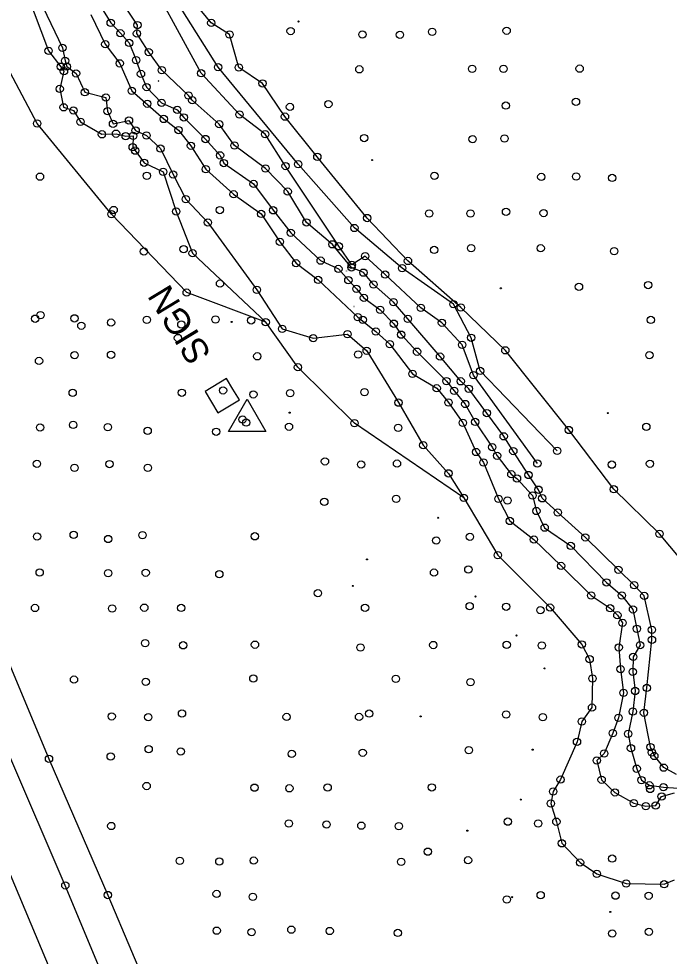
# Model space of a CAD drawing. Extents: x 20503438 to 20508873, y 7964251 to 7984667.
# Drawn here: x 20506200.2 to 20506378.1, y 7975825.9 to 7976082.3 of the extents above; entities that cross this region are included whole.
import ezdxf

# ---------------------------------------------------------------- set-up
doc = ezdxf.new("R2010")
doc.units = 0
for name, color, linetype in [('SurBreakLine', 7, 'Continuous'), ('SurControl', 7, 'Continuous'), ('SurDrainageArrowUp', 7, 'Continuous'), ('SurEdgeRoadPaved', 7, 'Continuous'), ('SurPointsNonDTM', 7, 'Continuous'), ('SurRoadPoints', 7, 'Continuous'), ('SurROWRail', 7, 'Continuous'), ('SurSurveyPoints', 7, 'Continuous'), ('SurTopOfWater', 7, 'Continuous')]:
    doc.layers.add(name, color=color, linetype=linetype)

msp = doc.modelspace()

# ---------------------------------------------------------------- linework, layer by layer
at = {"layer": 'SurBreakLine'}
for points in [[(20505948.4, 7976440.27), (20505966.85, 7976397.06), (20506023.36, 7976261.75), (20506041.13, 7976219.76), (20506046.8, 7976206.26), (20506065.51, 7976161.54), (20506080.11, 7976126.62), (20506096.34, 7976088.07), (20506109.89, 7976056.1), (20506152.29, 7975956.2), (20506170.93, 7975911.54), (20506188.78, 7975869.57), (20506237.85, 7975752.64), (20506255.76, 7975710.06), (20506257.96, 7975704.85), (20506266.89, 7975683.65), (20506275.92, 7975662.23), (20506291.46, 7975625.08), (20506306.43, 7975588.4), (20506320.89, 7975553.64), (20506349.14, 7975482.98), (20506362.94, 7975447.73)], [(20506321.91, 7975951.28), (20506292.04, 7975971.7), (20506276.55, 7975986.99), (20506267.72, 7975999.31), (20506246.1, 7976007.41), (20506225.53, 7976028.87), (20506205.19, 7976053.67), (20506197.03, 7976069.21), (20506190.03, 7976084.37), (20506184.41, 7976093.4), (20506177.2, 7976103.38), (20506168.01, 7976123.8)], [(20506347.48, 7975964.11), (20506326.41, 7975985.98), (20506323.96, 7975995.07), (20506319.08, 7976004.25), (20506305.08, 7976014.1), (20506291.99, 7976025.09), (20506276.63, 7976042.56), (20506254.69, 7976069.09), (20506237.54, 7976096.31), (20506234.05, 7976102.52), (20506225.9, 7976107.8)], [(20506342.05, 7975960.65), (20506324.59, 7975984.81), (20506321.5, 7975993.11), (20506315.95, 7975999.17), (20506310.19, 7976003.24), (20506300.42, 7976012.34), (20506294.96, 7976017.37), (20506291.29, 7976015), (20506287.74, 7976020.08), (20506273.17, 7976042.03), (20506267.6, 7976050.75), (20506260.55, 7976056.13), (20506250.08, 7976067.42), (20506232.79, 7976099.11)], [(20506380.12, 7975875.61), (20506376.63, 7975877.46), (20506374.06, 7975880.65), (20506372.99, 7975883.09), (20506371.22, 7975892.49), (20506371.99, 7975899.27), (20506373.41, 7975912.41), (20506373.4, 7975915.16), (20506371.3, 7975924.44), (20506368.54, 7975927.36), (20506364.22, 7975931.61), (20506355.18, 7975940.45), (20506347.67, 7975947.24), (20506343.39, 7975951.14), (20506342.38, 7975953.5), (20506339.64, 7975957.52), (20506335.47, 7975964.07), (20506332.84, 7975968.1), (20506328.25, 7975974.47), (20506323.28, 7975981.12), (20506321.08, 7975983.15), (20506315.42, 7975989.91), (20506306.62, 7976000.26), (20506302.69, 7976004.82), (20506297.24, 7976009.64), (20506294.46, 7976012.87), (20506291.2, 7976014.32), (20506285.97, 7976020.62), (20506278.88, 7976026.62), (20506273.74, 7976035.04), (20506267.69, 7976041.37), (20506259.2, 7976047.67), (20506255.02, 7976053.46), (20506247.64, 7976060.03), (20506246.6, 7976061.33), (20506239.3, 7976068.27), (20506235.72, 7976073.22), (20506232.49, 7976078.26), (20506232.64, 7976080.6), (20506225.6, 7976091.26)], [(20506381.1, 7975934.72), (20506375.49, 7975941.43), (20506362.97, 7975953.61), (20506350.67, 7975969.83), (20506333.29, 7975991.62), (20506321.12, 7976003.33), (20506306.65, 7976016.07), (20506295.48, 7976027.82), (20506281.85, 7976044.54), (20506273, 7976055.55), (20506266.84, 7976064.65), (20506260.39, 7976069.01), (20506257.81, 7976078.04), (20506252.83, 7976081.18), (20506244.7, 7976091.19)], [(20506202.28, 7976089.62), (20506208.32, 7976073.55), (20506211.69, 7976069.22), (20506212.53, 7976067.98), (20506211.37, 7976063.13), (20506212.44, 7976058.1), (20506215.1, 7976057.24), (20506217.03, 7976054.15), (20506222.92, 7976050.72), (20506226.77, 7976050.89), (20506229.41, 7976050.21), (20506231.48, 7976050.28), (20506231.33, 7976047.2), (20506231.99, 7976046.25), (20506234.45, 7976042.95), (20506239.67, 7976040.44), (20506243.25, 7976029.61), (20506247.73, 7976018.17), (20506267.72, 7975999.31)], [(20506205.75, 7976087.79), (20506212.1, 7976074.39), (20506212.83, 7976070.83), (20506213.32, 7976069.24), (20506215.84, 7976067.38), (20506218.22, 7976062.22), (20506224.01, 7976060.8), (20506224.47, 7976057.05), (20506225.95, 7976053.6), (20506230.32, 7976054.48), (20506232.14, 7976051.76), (20506235.12, 7976050.41), (20506238.92, 7976046.8), (20506242.38, 7976039.73), (20506245.88, 7976032.99), (20506251.92, 7976026.58), (20506265.31, 7976008.18), (20506272.23, 7975997.51), (20506280.74, 7975994.95), (20506290.1, 7975996.06), (20506295.35, 7975991.51), (20506304.05, 7975977.31), (20506310.84, 7975965.69), (20506317.76, 7975957.97), (20506321.91, 7975951.28), (20506331.23, 7975935.61), (20506345.53, 7975921.24), (20506354.23, 7975911.18), (20506356.36, 7975907.13), (20506357.14, 7975901.83), (20506357, 7975893.89), (20506354.2, 7975890.08), (20506352.9, 7975884.52), (20506348.41, 7975874.19), (20506346.37, 7975870.95), (20506345.72, 7975867.65), (20506347.25, 7975862.68), (20506348.75, 7975856.76), (20506353.74, 7975851.48), (20506358.31, 7975848.43), (20506366.37, 7975845.79), (20506376.74, 7975845.56), (20506379.54, 7975846.75)], [(20506219.84, 7976083.45), (20506223.83, 7976075.35), (20506227.78, 7976070.13), (20506231.07, 7976062.59), (20506239.83, 7976054.91), (20506243.85, 7976051.88), (20506247.27, 7976047.59), (20506251.35, 7976041.16), (20506258.95, 7976034.32), (20506266.48, 7976028.93), (20506271.62, 7976021.32), (20506276.03, 7976015.44), (20506282.07, 7976010.88), (20506292.92, 7976000.7), (20506297.88, 7975996.79), (20506301.7, 7975993.31), (20506307.9, 7975985.19), (20506314.51, 7975981.24), (20506317.72, 7975977.36), (20506321.68, 7975971.79), (20506325.28, 7975963.81), (20506327.31, 7975960.94), (20506331.41, 7975951.01), (20506334.53, 7975944.94), (20506341.12, 7975939.87), (20506348.54, 7975932.64), (20506356.77, 7975924.55), (20506361.98, 7975921.06), (20506363.94, 7975919.15), (20506365.37, 7975917.09), (20506364.31, 7975910.36), (20506364.83, 7975904.4), (20506365.64, 7975897.93), (20506364.27, 7975891.09), (20506362.69, 7975886.89), (20506360.35, 7975881.32), (20506358.29, 7975879.43), (20506359.64, 7975874.16), (20506363.28, 7975870.7), (20506368.46, 7975867.73), (20506371.74, 7975866.91), (20506374.43, 7975867.13), (20506376.06, 7975869.56), (20506379.62, 7975870.57)]]:
    msp.add_lwpolyline(points, dxfattribs=at)
at = {"layer": 'SurControl'}
for centre in [(20506276.68, 7976081.57), (20506296.84, 7976043.67), (20506332.07, 7976008.59), (20506258.41, 7975999.4), (20506274.28, 7975974.56), (20506361.31, 7975974.46), (20506314.9, 7975945.83), (20506295.44, 7975934.42), (20506291.55, 7975927.17), (20506325.14, 7975924.27), (20506336.34, 7975913.62), (20506344.02, 7975904.61), (20506310.11, 7975891.47), (20506340.77, 7975882.38), (20506337.51, 7975868.72), (20506322.89, 7975860.22), (20506335.18, 7975842.04), (20506362.01, 7975838)]:
    msp.add_circle(centre, 0.15, dxfattribs=at)
at = {"layer": 'SurDrainageArrowUp'}
msp.add_lwpolyline([(20506222.76, 7976085.29), (20506225.31, 7976081.21), (20506227.96, 7976078.36), (20506230.37, 7976075.71), (20506232.27, 7976071.01), (20506233.6, 7976067.23), (20506235.14, 7976063.64), (20506239.24, 7976059.31), (20506243.53, 7976057.41), (20506245.34, 7976055.35), (20506251.24, 7976049.43), (20506255.24, 7976044.96), (20506256.26, 7976042.85), (20506264.41, 7976037.14), (20506269.78, 7976029.93), (20506274.57, 7976023.8), (20506282.76, 7976016.16), (20506287.61, 7976013.89), (20506290.34, 7976010.8), (20506292.54, 7976008.43), (20506294.6, 7976005.96), (20506299.04, 7976002.7), (20506302.79, 7975998.91), (20506304.77, 7975995.91), (20506309.13, 7975991.25), (20506317.18, 7975983.21), (20506319.3, 7975980.55), (20506322.33, 7975976.94), (20506325.03, 7975972.04), (20506329.72, 7975965.15), (20506331.03, 7975962.79), (20506334.93, 7975957.72), (20506336.48, 7975956.57), (20506340.71, 7975951.9), (20506341.79, 7975947.67), (20506344.05, 7975943.11), (20506351.19, 7975938.11), (20506360.96, 7975928.14), (20506365.17, 7975924.54), (20506368.22, 7975920.75), (20506369.27, 7975915.46), (20506370.15, 7975910.98), (20506368.3, 7975907.79), (20506368.15, 7975903.66), (20506368.8, 7975898.44), (20506368.17, 7975892.8), (20506366.9, 7975886.71), (20506367.67, 7975882.77), (20506369.24, 7975877.18), (20506370.56, 7975874.06), (20506372.71, 7975872.63), (20506376.54, 7975872.14), (20506383.34, 7975871.63)], dxfattribs=at)
at = {"layer": 'SurEdgeRoadPaved'}
for points in [[(20505973.34, 7976438.98), (20505987.53, 7976403.61), (20506003.07, 7976367.49), (20506018.95, 7976328.88), (20506025.44, 7976313.31), (20506044.67, 7976267.48), (20506061.06, 7976228.29), (20506067.76, 7976212.43), (20506081.36, 7976180.25), (20506103.2, 7976128.63), (20506112.1, 7976107.56), (20506128.65, 7976068.25), (20506136.4, 7976049.83), (20506153.65, 7976009.14), (20506168.49, 7975974.01), (20506178.44, 7975950.63), (20506193.04, 7975916.4), (20506208.43, 7975879.89), (20506224.55, 7975842.62), (20506237.48, 7975811.98)], [(20506375.71, 7975448.39), (20506362.64, 7975481.5), (20506329.83, 7975562.96), (20506317.59, 7975593.18), (20506238.7, 7975783.34), (20506212.9, 7975845.26), (20506167.37, 7975951.08), (20506129.46, 7976040.57), (20506122.49, 7976056.94), (20506110.39, 7976085.68), (20506105.99, 7976096.14), (20506091.81, 7976130.11), (20506074.2, 7976171.54), (20506054.82, 7976217.77), (20506019.21, 7976302.51), (20505976.84, 7976403.26), (20505970.11, 7976419.35)]]:
    msp.add_lwpolyline(points, dxfattribs=at)
at = {"layer": 'SurPointsNonDTM'}
for centre in [(20506206.12, 7976001.25), (20506217.28, 7975998.36), (20506243.71, 7975994.99), (20506256.06, 7975980.67), (20506261.4, 7975972.72), (20506262.4, 7975971.85), (20506282.02, 7975925.2), (20506296.02, 7975892.25), (20506312.07, 7975854.48)]:
    msp.add_circle(centre, 1, dxfattribs=at)
at = {"layer": 'SurRoadPoints'}
msp.add_lwpolyline([(20506258.75, 7975980.99), (20506258.75, 7975980.99), (20506256.97, 7975983.92), (20506251.12, 7975980.37), (20506254.67, 7975974.5), (20506260.53, 7975978.05), (20506258.75, 7975980.98)], dxfattribs=at)
at = {"layer": 'SurROWRail'}
msp.add_lwpolyline([(20506262.64, 7975978.27), (20506267.73, 7975969.45), (20506257.55, 7975969.45)], close=True, dxfattribs=at)
at = {"layer": 'SurSurveyPoints'}
for centre in [(20506225.31, 7976081.21), (20506232.64, 7976080.6), (20506252.83, 7976081.18), (20506227.96, 7976078.36), (20506232.49, 7976078.26), (20506257.81, 7976078.04), (20506274.55, 7976078.96), (20506294.18, 7976078.04), (20506304.46, 7976077.93), (20506313.26, 7976078.73), (20506333.65, 7976079.06), (20506212.1, 7976074.39), (20506223.83, 7976075.35), (20506230.37, 7976075.71), (20506208.32, 7976073.55), (20506235.72, 7976073.22), (20506211.69, 7976069.22), (20506212.83, 7976070.83), (20506213.32, 7976069.24), (20506227.78, 7976070.13), (20506232.27, 7976071.01), (20506212.53, 7976067.98), (20506215.84, 7976067.38), (20506233.6, 7976067.23), (20506239.3, 7976068.27), (20506250.08, 7976067.42), (20506254.69, 7976069.09), (20506260.39, 7976069.01), (20506293.34, 7976068.5), (20506324.22, 7976068.62), (20506332.81, 7976068.63), (20506353.62, 7976068.68), (20506266.84, 7976064.65), (20506211.37, 7976063.13), (20506218.22, 7976062.22), (20506231.07, 7976062.59), (20506235.14, 7976063.64), (20506224.01, 7976060.8), (20506235.32, 7976059.09), (20506239.24, 7976059.31), (20506246.6, 7976061.33), (20506247.64, 7976060.03), (20506284.88, 7976058.99), (20506352.62, 7976059.61), (20506212.44, 7976058.1), (20506215.1, 7976057.24), (20506224.47, 7976057.05), (20506243.53, 7976057.41), (20506274.35, 7976058.2), (20506333.42, 7976058.57), (20506217.03, 7976054.15), (20506230.32, 7976054.48), (20506239.83, 7976054.91), (20506245.34, 7976055.35), (20506260.55, 7976056.13), (20506273, 7976055.55), (20506205.19, 7976053.67), (20506225.95, 7976053.6), (20506232.14, 7976051.76), (20506243.85, 7976051.88), (20506255.02, 7976053.46), (20506222.92, 7976050.72), (20506226.77, 7976050.89), (20506229.41, 7976050.21), (20506231.48, 7976050.28), (20506235.12, 7976050.41), (20506251.24, 7976049.43), (20506267.6, 7976050.75), (20506294.68, 7976049.69), (20506324.34, 7976049.37), (20506333.06, 7976049.59), (20506231.33, 7976047.2), (20506231.99, 7976046.25), (20506238.92, 7976046.8), (20506247.27, 7976047.59), (20506259.2, 7976047.67), (20506255.24, 7976044.96), (20506281.85, 7976044.54), (20506234.45, 7976042.95), (20506251.35, 7976041.16), (20506256.26, 7976042.85), (20506267.69, 7976041.37), (20506273.17, 7976042.03), (20506276.63, 7976042.56), (20506205.97, 7976039.13), (20506235.18, 7976039.38), (20506239.67, 7976040.44), (20506242.38, 7976039.73), (20506313.88, 7976039.35), (20506343.13, 7976039.06), (20506352.66, 7976039.16), (20506362.51, 7976038.78), (20506264.41, 7976037.14), (20506258.95, 7976034.32), (20506273.74, 7976035.04), (20506245.88, 7976032.99), (20506225.53, 7976028.87), (20506226.12, 7976030.01), (20506243.25, 7976029.61), (20506255.17, 7976029.99), (20506266.48, 7976028.93), (20506269.78, 7976029.93), (20506312.46, 7976029.05), (20506323.77, 7976029.07), (20506333.48, 7976029.5), (20506343.76, 7976029.17), (20506251.92, 7976026.58), (20506278.88, 7976026.62), (20506295.48, 7976027.82), (20506274.57, 7976023.8), (20506291.99, 7976025.09), (20506271.62, 7976021.32), (20506285.97, 7976020.62), (20506234.41, 7976018.66), (20506245.27, 7976019.31), (20506247.73, 7976018.17), (20506287.74, 7976020.08), (20506313.8, 7976019.09), (20506323.92, 7976019.59), (20506342.97, 7976019.54), (20506363.06, 7976018.73), (20506276.03, 7976015.44), (20506282.76, 7976016.16), (20506294.96, 7976017.37), (20506306.65, 7976016.07), (20506287.61, 7976013.89), (20506291.2, 7976014.32), (20506291.29, 7976015), (20506294.46, 7976012.87), (20506305.08, 7976014.1), (20506282.07, 7976010.88), (20506290.34, 7976010.8), (20506300.42, 7976012.34), (20506255.22, 7976009.87), (20506265.31, 7976008.18), (20506292.54, 7976008.43), (20506297.24, 7976009.64), (20506353.44, 7976009.01), (20506372.35, 7976009.48), (20506246.1, 7976007.41), (20506294.6, 7976005.96), (20506299.04, 7976002.7), (20506302.69, 7976004.82), (20506310.19, 7976003.24), (20506319.08, 7976004.25), (20506321.12, 7976003.33), (20506204.66, 7976000.28), (20506215.39, 7976000.37), (20506235.22, 7975999.97), (20506253.97, 7976000.06), (20506292.92, 7976000.7), (20506294.27, 7975999.97), (20506306.62, 7976000.26), (20506373.08, 7975999.94), (20506225.41, 7975999.21), (20506244.64, 7975998.69), (20506263.76, 7975999.82), (20506267.72, 7975999.31), (20506272.23, 7975997.51), (20506302.79, 7975998.91), (20506315.95, 7975999.17), (20506280.74, 7975994.95), (20506290.1, 7975996.06), (20506297.88, 7975996.79), (20506304.77, 7975995.91), (20506323.96, 7975995.07), (20506301.7, 7975993.31), (20506321.5, 7975993.11), (20506215.44, 7975990.31), (20506225.4, 7975990.38), (20506265.42, 7975989.99), (20506293.04, 7975990.47), (20506295.35, 7975991.51), (20506309.13, 7975991.25), (20506315.42, 7975989.91), (20506333.29, 7975991.62), (20506372.71, 7975990.28), (20506205.7, 7975988.72), (20506276.55, 7975986.99), (20506307.9, 7975985.19), (20506324.59, 7975984.81), (20506326.41, 7975985.98), (20506317.18, 7975983.21), (20506321.08, 7975983.15), (20506214.91, 7975979.99), (20506244.77, 7975980.03), (20506264.35, 7975979.57), (20506274.41, 7975979.91), (20506294.74, 7975980.16), (20506314.51, 7975981.24), (20506319.3, 7975980.55), (20506323.28, 7975981.12), (20506304.05, 7975977.31), (20506317.72, 7975977.36), (20506322.33, 7975976.94), (20506328.25, 7975974.47), (20506292.04, 7975971.7), (20506321.68, 7975971.79), (20506325.03, 7975972.04), (20506205.98, 7975970.5), (20506215.03, 7975971.22), (20506224.54, 7975970.6), (20506235.43, 7975969.59), (20506254.18, 7975969.36), (20506274.1, 7975970.73), (20506303.97, 7975970.43), (20506350.67, 7975969.83), (20506371.87, 7975970.68), (20506332.84, 7975968.1), (20506310.84, 7975965.69), (20506329.72, 7975965.15), (20506335.47, 7975964.07), (20506347.48, 7975964.11), (20506325.28, 7975963.81), (20506331.03, 7975962.79), (20506205.13, 7975960.57), (20506215.4, 7975959.46), (20506224.98, 7975960.51), (20506235.48, 7975959.49), (20506283.94, 7975961.24), (20506293.82, 7975960.39), (20506303.65, 7975960.63), (20506327.31, 7975960.94), (20506342.05, 7975960.65), (20506362.44, 7975960.35), (20506372.85, 7975960.61), (20506317.76, 7975957.97), (20506334.93, 7975957.72), (20506336.48, 7975956.57), (20506339.64, 7975957.52), (20506321.91, 7975951.28), (20506340.71, 7975951.9), (20506342.38, 7975953.5), (20506362.97, 7975953.61), (20506283.76, 7975950.16), (20506303.41, 7975950.98), (20506331.41, 7975951.01), (20506333.86, 7975950.54), (20506343.39, 7975951.14), (20506341.79, 7975947.67), (20506347.67, 7975947.24), (20506334.53, 7975944.94), (20506215.18, 7975941.14), (20506234, 7975941.08), (20506344.05, 7975943.11), (20506375.49, 7975941.43), (20506205.16, 7975940.7), (20506224.63, 7975940.01), (20506264.73, 7975940.75), (20506314.4, 7975939.61), (20506323.6, 7975940.6), (20506341.12, 7975939.87), (20506355.18, 7975940.45), (20506351.19, 7975938.11), (20506331.23, 7975935.61), (20506205.88, 7975930.84), (20506224.62, 7975930.66), (20506234.89, 7975930.79), (20506313.77, 7975930.82), (20506323.17, 7975931.67), (20506348.54, 7975932.64), (20506364.22, 7975931.61), (20506255.04, 7975930.41), (20506360.96, 7975928.14), (20506368.54, 7975927.36), (20506356.77, 7975924.55), (20506365.17, 7975924.54), (20506371.3, 7975924.44), (20506204.6, 7975921.14), (20506225.73, 7975921.01), (20506234.51, 7975921.22), (20506244.59, 7975921.15), (20506294.9, 7975921.2), (20506323.53, 7975921.65), (20506333.52, 7975921.49), (20506342.88, 7975920.55), (20506345.53, 7975921.24), (20506361.98, 7975921.06), (20506368.22, 7975920.75), (20506363.94, 7975919.15), (20506365.37, 7975917.09), (20506369.27, 7975915.46), (20506373.4, 7975915.16), (20506234.76, 7975911.5), (20506245.16, 7975910.93), (20506264.79, 7975911.1), (20506293.68, 7975910.34), (20506313.58, 7975911.01), (20506333.66, 7975911.05), (20506343.29, 7975910.89), (20506354.23, 7975911.18), (20506364.31, 7975910.36), (20506370.15, 7975910.98), (20506373.41, 7975912.41), (20506368.3, 7975907.79), (20506356.36, 7975907.13), (20506364.83, 7975904.4), (20506368.15, 7975903.66), (20506215.27, 7975901.55), (20506234.9, 7975900.92), (20506264.34, 7975901.84), (20506303.32, 7975901.77), (20506323.76, 7975900.83), (20506357.14, 7975901.83), (20506365.64, 7975897.93), (20506368.8, 7975898.44), (20506371.99, 7975899.27), (20506244.82, 7975892.29), (20506357, 7975893.89), (20506368.17, 7975892.8), (20506371.22, 7975892.49), (20506225.59, 7975891.48), (20506235.59, 7975891.27), (20506273.44, 7975891.34), (20506293.26, 7975891.34), (20506333.53, 7975892.01), (20506343.54, 7975891.26), (20506354.2, 7975890.08), (20506364.27, 7975891.09), (20506352.9, 7975884.52), (20506362.69, 7975886.89), (20506366.9, 7975886.71), (20506235.7, 7975882.51), (20506323.28, 7975882.24), (20506367.67, 7975882.77), (20506372.99, 7975883.09), (20506208.43, 7975879.89), (20506225.31, 7975880.53), (20506244.47, 7975881.88), (20506274.84, 7975881.22), (20506294.26, 7975881.54), (20506358.29, 7975879.43), (20506360.35, 7975881.32), (20506373.38, 7975881.63), (20506374.06, 7975880.65), (20506369.24, 7975877.18), (20506376.63, 7975877.46), (20506235.15, 7975872.44), (20506264.67, 7975871.99), (20506274.2, 7975871.81), (20506284.67, 7975872.02), (20506313.19, 7975872.06), (20506348.41, 7975874.19), (20506359.64, 7975874.16), (20506370.56, 7975874.06), (20506372.71, 7975872.63), (20506376.54, 7975872.14), (20506346.37, 7975870.95), (20506363.28, 7975870.7), (20506372.91, 7975871.62), (20506376.06, 7975869.56), (20506345.72, 7975867.65), (20506368.46, 7975867.73), (20506371.74, 7975866.91), (20506374.43, 7975867.13), (20506225.47, 7975861.5), (20506274.06, 7975862.19), (20506284.39, 7975861.93), (20506293.89, 7975861.59), (20506304.15, 7975861.47), (20506333.97, 7975862.69), (20506342.28, 7975862.2), (20506347.25, 7975862.68), (20506348.75, 7975856.76), (20506244.23, 7975851.96), (20506255.04, 7975851.78), (20506264.45, 7975852.03), (20506304.78, 7975851.71), (20506323.09, 7975852.13), (20506353.74, 7975851.48), (20506362.52, 7975852.58), (20506358.31, 7975848.43), (20506212.9, 7975845.26), (20506366.37, 7975845.79), (20506376.74, 7975845.56), (20506224.55, 7975842.62), (20506254.29, 7975842.92), (20506264.19, 7975842.14), (20506333.71, 7975841.4), (20506342.96, 7975842.59), (20506363.44, 7975842.45), (20506372.51, 7975842.43), (20506254.32, 7975832.87), (20506263.87, 7975832.47), (20506274.74, 7975833.14), (20506285.24, 7975832.78), (20506303.86, 7975832.24), (20506362.55, 7975832.09), (20506372.58, 7975832.57)]:
    msp.add_circle(centre, 1, dxfattribs=at)
at = {"layer": 'SurTopOfWater'}
for points in [[(20506238.4, 7976065.27), (20506238.44, 7976065.27), (20506238.44, 7976065.31), (20506238.4, 7976065.31)], [(20506238.42, 7976065.32), (20506238.42, 7976065.32), (20506238.42, 7976065.28), (20506238.42, 7976065.28)], [(20506238.42, 7976065.32), (20506238.42, 7976065.32), (20506238.42, 7976065.3), (20506238.42, 7976065.3)], [(20506238.42, 7976065.3), (20506238.42, 7976065.3), (20506238.42, 7976065.29), (20506238.42, 7976065.29)], [(20506238.42, 7976065.29), (20506238.42, 7976065.29), (20506238.42, 7976065.28), (20506238.42, 7976065.28)], [(20506289.83, 7976013.28), (20506289.87, 7976013.28), (20506289.87, 7976013.32), (20506289.83, 7976013.32)], [(20506289.85, 7976013.33), (20506289.85, 7976013.33), (20506289.85, 7976013.29), (20506289.85, 7976013.29)], [(20506289.85, 7976013.33), (20506289.85, 7976013.33), (20506289.85, 7976013.31), (20506289.85, 7976013.31)], [(20506289.85, 7976013.31), (20506289.85, 7976013.31), (20506289.85, 7976013.3), (20506289.85, 7976013.3)], [(20506289.85, 7976013.3), (20506289.85, 7976013.3), (20506289.85, 7976013.29), (20506289.85, 7976013.29)], [(20506291.86, 7976003.6), (20506291.9, 7976003.6), (20506291.9, 7976003.64), (20506291.86, 7976003.64)], [(20506291.88, 7976003.65), (20506291.88, 7976003.65), (20506291.88, 7976003.61), (20506291.88, 7976003.61)], [(20506291.88, 7976003.65), (20506291.88, 7976003.65), (20506291.88, 7976003.63), (20506291.88, 7976003.63)], [(20506291.88, 7976003.63), (20506291.88, 7976003.63), (20506291.88, 7976003.62), (20506291.88, 7976003.62)], [(20506291.88, 7976003.62), (20506291.88, 7976003.62), (20506291.88, 7976003.61), (20506291.88, 7976003.61)], [(20506336.33, 7975956.09), (20506336.37, 7975956.09), (20506336.37, 7975956.13), (20506336.33, 7975956.13)], [(20506336.35, 7975956.14), (20506336.35, 7975956.14), (20506336.35, 7975956.1), (20506336.35, 7975956.1)], [(20506336.35, 7975956.14), (20506336.35, 7975956.14), (20506336.35, 7975956.12), (20506336.35, 7975956.12)], [(20506336.35, 7975956.12), (20506336.35, 7975956.12), (20506336.35, 7975956.11), (20506336.35, 7975956.11)], [(20506336.35, 7975956.11), (20506336.35, 7975956.11), (20506336.35, 7975956.1), (20506336.35, 7975956.1)], [(20506368.89, 7975914.45), (20506368.93, 7975914.45), (20506368.93, 7975914.49), (20506368.89, 7975914.49)], [(20506368.91, 7975914.5), (20506368.91, 7975914.5), (20506368.91, 7975914.46), (20506368.91, 7975914.46)], [(20506368.91, 7975914.5), (20506368.91, 7975914.5), (20506368.91, 7975914.48), (20506368.91, 7975914.48)], [(20506368.91, 7975914.48), (20506368.91, 7975914.48), (20506368.91, 7975914.47), (20506368.91, 7975914.47)], [(20506368.91, 7975914.47), (20506368.91, 7975914.47), (20506368.91, 7975914.46), (20506368.91, 7975914.46)], [(20506369.32, 7975907.11), (20506369.36, 7975907.11), (20506369.36, 7975907.15), (20506369.32, 7975907.15)], [(20506369.34, 7975907.16), (20506369.34, 7975907.16), (20506369.34, 7975907.12), (20506369.34, 7975907.12)], [(20506369.34, 7975907.16), (20506369.34, 7975907.16), (20506369.34, 7975907.14), (20506369.34, 7975907.14)], [(20506369.34, 7975907.14), (20506369.34, 7975907.14), (20506369.34, 7975907.13), (20506369.34, 7975907.13)], [(20506369.34, 7975907.13), (20506369.34, 7975907.13), (20506369.34, 7975907.12), (20506369.34, 7975907.12)]]:
    msp.add_lwpolyline(points, close=True, dxfattribs=at)
for centre in [(20506238.41, 7976065.29), (20506238.42, 7976065.29), (20506238.43, 7976065.29), (20506289.84, 7976013.3), (20506289.85, 7976013.3), (20506289.86, 7976013.3), (20506291.87, 7976003.62), (20506291.88, 7976003.62), (20506291.89, 7976003.62), (20506336.34, 7975956.11), (20506336.35, 7975956.11), (20506336.36, 7975956.11), (20506368.9, 7975914.47), (20506368.91, 7975914.47), (20506368.92, 7975914.47), (20506369.33, 7975907.13), (20506369.34, 7975907.13), (20506369.35, 7975907.13)]:
    msp.add_arc(centre, 0.00586, 186.3566, 5.6839, dxfattribs=at)

# ---------------------------------------------------------------- texts
at = {"layer": 'SurRoadPoints'}
msp.add_text('SIGN', height=6.995, rotation=121.2047, dxfattribs=at).set_placement((20506253.01, 7975990.61))

doc.saveas('drawing.dxf')
